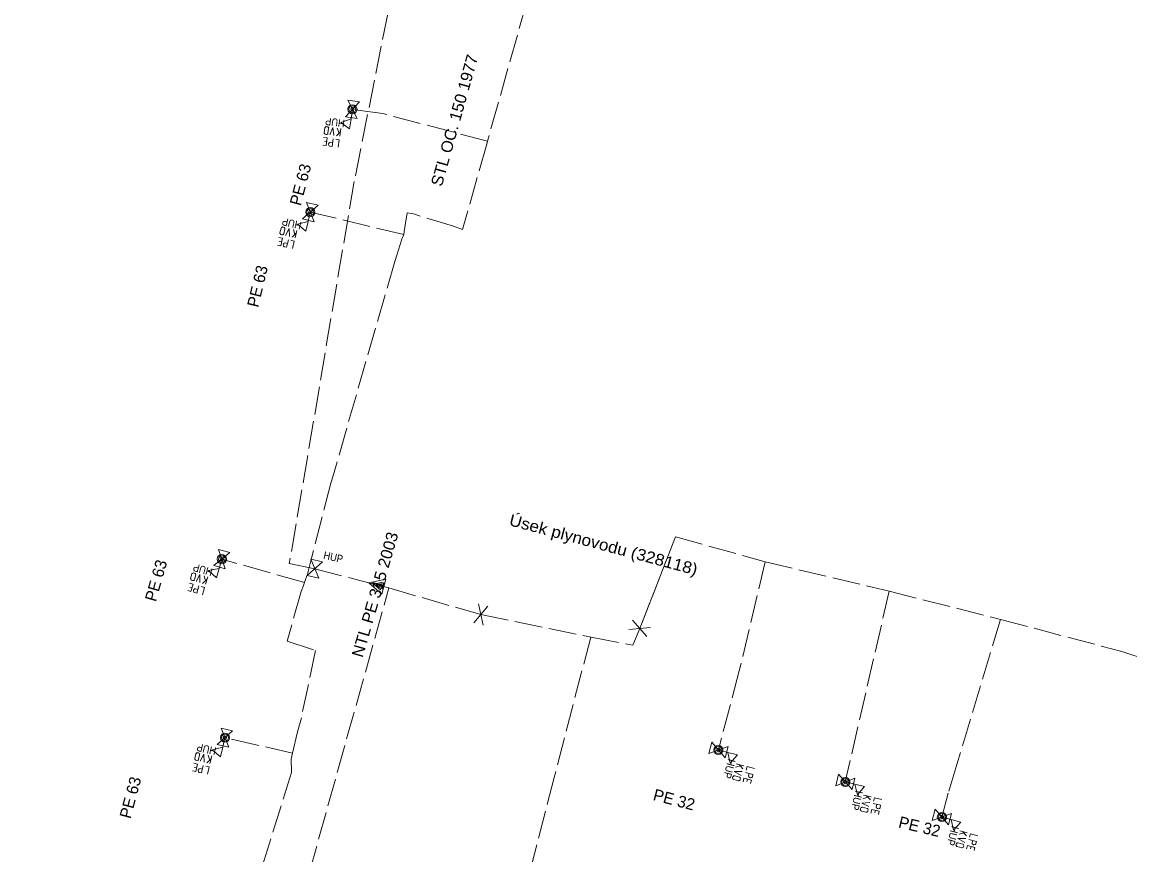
# Model space of a CAD drawing. Extents: x -688140 to -687678, y -1056859 to -1056384.
# Drawn here: x -688074.2 to -688002.5, y -1056647.4 to -1056593.5 of the extents above; entities that cross this region are included whole.
import ezdxf
from ezdxf.enums import TextEntityAlignment as Align

# ---------------------------------------------------------------- set-up
doc = ezdxf.new("R2010")
doc.units = 0
doc.header["$LTSCALE"] = 0.3
doc.linetypes.add('LONG_DASHED', pattern=[7.5, 6, -1.5])
for name, color, linetype, lineweight in [('12', 7, 'Continuous', 13), ('13', 7, 'Continuous', 13), ('25', 7, 'Continuous', 13), ('35', 7, 'LONG_DASHED', 13), ('40', 7, 'LONG_DASHED', 13), ('50', 7, 'LONG_DASHED', 13)]:
    doc.layers.add(name, color=color, linetype=linetype, lineweight=lineweight)
doc.layers.add('15', color=7, linetype='Continuous')

msp = doc.modelspace()

# ---------------------------------------------------------------- linework, layer by layer
at = {"layer": '12'}
for p, q in [((-688053.288, -1056599.585), (-688052.372, -1056598.615)), ((-688052.372, -1056598.615), (-688053.134, -1056598.506)), ((-688052.526, -1056599.694), (-688053.134, -1056598.506)), ((-688052.83, -1056599.1), (-688052.919, -1056599.724)), ((-688052.526, -1056599.694), (-688053.288, -1056599.585)), ((-688054.662, -1056600.617), (-688054.618, -1056600.31)), ((-688054.371, -1056600.346), (-688054.414, -1056600.653)), ((-688053.611, -1056600.544), (-688053.853, -1056600.823)), ((-688053.686, -1056600.645), (-688053.812, -1056600.324)), ((-688053.655, -1056600.851), (-688053.584, -1056600.356)), ((-688054.65, -1056601.175), (-688054.492, -1056601.197)), ((-688054.265, -1056601.239), (-688054.107, -1056601.262)), ((-688056.061, -1056606.2), (-688055.059, -1056605.32)), ((-688055.059, -1056605.32), (-688055.807, -1056605.14)), ((-688055.313, -1056606.38), (-688055.807, -1056605.14)), ((-688055.56, -1056605.76), (-688055.707, -1056606.373)), ((-688055.313, -1056606.38), (-688056.061, -1056606.2)), ((-688057.526, -1056607.099), (-688057.454, -1056606.797)), ((-688057.211, -1056606.855), (-688057.283, -1056607.157)), ((-688056.473, -1056607.125), (-688056.74, -1056607.38)), ((-688056.557, -1056607.218), (-688056.653, -1056606.886)), ((-688056.545, -1056607.426), (-688056.429, -1056606.94)), ((-688057.567, -1056607.655), (-688057.411, -1056607.692)), ((-688057.19, -1056607.755), (-688057.034, -1056607.792)), ((-688061.809, -1056628.649), (-688060.771, -1056627.811)), ((-688060.771, -1056627.811), (-688061.511, -1056627.601)), ((-688061.069, -1056628.859), (-688061.511, -1056627.601)), ((-688061.069, -1056628.859), (-688061.809, -1056628.649)), ((-688061.29, -1056628.23), (-688061.462, -1056628.836)), ((-688063.31, -1056629.486), (-688063.225, -1056629.188)), ((-688062.985, -1056629.256), (-688063.07, -1056629.554)), ((-688062.347, -1056629.645), (-688062.428, -1056629.31)), ((-688062.344, -1056629.854), (-688062.207, -1056629.373)), ((-688063.374, -1056630.039), (-688063.22, -1056630.083)), ((-688063.001, -1056630.156), (-688062.847, -1056630.199)), ((-688062.259, -1056629.556), (-688062.536, -1056629.799)), ((-688061.588, -1056640.235), (-688060.592, -1056639.345)), ((-688060.592, -1056639.345), (-688061.343, -1056639.172)), ((-688060.837, -1056640.408), (-688061.343, -1056639.172)), ((-688060.837, -1056640.408), (-688061.588, -1056640.235)), ((-688061.09, -1056639.79), (-688061.232, -1056640.404)), ((-688063.044, -1056641.146), (-688062.975, -1056640.843)), ((-688062.731, -1056640.9), (-688062.801, -1056641.202)), ((-688062.075, -1056641.256), (-688062.173, -1056640.926)), ((-688062.061, -1056641.465), (-688061.949, -1056640.977)), ((-688063.08, -1056641.702), (-688062.924, -1056641.738)), ((-688061.991, -1056641.163), (-688062.256, -1056641.42)), ((-688062.703, -1056641.799), (-688062.547, -1056641.835))]:
    msp.add_line(p, q, dxfattribs=at)
for points in [[(-688052.919, -1056599.724), (-688053.587, -1056599.952), (-688053.009, -1056600.357)], [(-688055.707, -1056606.373), (-688056.394, -1056606.537), (-688055.856, -1056606.995)], [(-688061.462, -1056628.836), (-688062.156, -1056628.972), (-688061.637, -1056629.452)], [(-688061.232, -1056640.404), (-688061.917, -1056640.574), (-688061.375, -1056641.028)]]:
    msp.add_lwpolyline(points, close=True, dxfattribs=at)
for points in [[(-688054.414, -1056600.653), (-688054.418, -1056600.682), (-688054.442, -1056600.709), (-688054.486, -1056600.733), (-688054.526, -1056600.728), (-688054.575, -1056600.721), (-688054.605, -1056600.716), (-688054.639, -1056600.671), (-688054.656, -1056600.648), (-688054.662, -1056600.617)], [(-688054.371, -1056600.346), (-688054.365, -1056600.306), (-688054.382, -1056600.283), (-688054.417, -1056600.248), (-688054.456, -1056600.233), (-688054.505, -1056600.225), (-688054.535, -1056600.221), (-688054.58, -1056600.255), (-688054.603, -1056600.272), (-688054.618, -1056600.31)], [(-688054.031, -1056600.798), (-688054.099, -1056600.283), (-688054.288, -1056600.761)], [(-688054.746, -1056601.423), (-688054.528, -1056601.454), (-688054.458, -1056600.959), (-688054.695, -1056600.926)], [(-688054.301, -1056601.487), (-688054.347, -1056601.46), (-688054.376, -1056601.375), (-688054.37, -1056601.336), (-688054.318, -1056601.252), (-688054.265, -1056601.239)], [(-688054.072, -1056601.014), (-688054.142, -1056601.509), (-688054.301, -1056601.487)], [(-688053.756, -1056601.564), (-688053.686, -1056601.069), (-688053.913, -1056601.037)], [(-688057.283, -1056607.157), (-688057.29, -1056607.186), (-688057.316, -1056607.211), (-688057.362, -1056607.23), (-688057.401, -1056607.221), (-688057.45, -1056607.21), (-688057.479, -1056607.203), (-688057.509, -1056607.154), (-688057.523, -1056607.13), (-688057.526, -1056607.099)], [(-688057.211, -1056606.855), (-688057.201, -1056606.817), (-688057.216, -1056606.792), (-688057.248, -1056606.754), (-688057.285, -1056606.735), (-688057.333, -1056606.723), (-688057.362, -1056606.716), (-688057.411, -1056606.746), (-688057.435, -1056606.761), (-688057.454, -1056606.797)], [(-688056.915, -1056607.338), (-688056.935, -1056606.819), (-688057.168, -1056607.277)], [(-688057.686, -1056607.893), (-688057.472, -1056607.945), (-688057.355, -1056607.458), (-688057.589, -1056607.402)], [(-688057.248, -1056607.998), (-688057.292, -1056607.967), (-688057.312, -1056607.88), (-688057.303, -1056607.841), (-688057.243, -1056607.763), (-688057.19, -1056607.755)], [(-688056.976, -1056607.549), (-688057.092, -1056608.036), (-688057.248, -1056607.998)], [(-688056.713, -1056608.126), (-688056.597, -1056607.64), (-688056.82, -1056607.587)], [(-688063.07, -1056629.554), (-688063.078, -1056629.583), (-688063.105, -1056629.606), (-688063.152, -1056629.624), (-688063.19, -1056629.613), (-688063.238, -1056629.6), (-688063.267, -1056629.591), (-688063.295, -1056629.542), (-688063.309, -1056629.517), (-688063.31, -1056629.486)], [(-688062.985, -1056629.256), (-688062.974, -1056629.217), (-688062.988, -1056629.193), (-688063.018, -1056629.153), (-688063.054, -1056629.132), (-688063.102, -1056629.119), (-688063.131, -1056629.111), (-688063.18, -1056629.138), (-688063.205, -1056629.152), (-688063.225, -1056629.188)], [(-688062.709, -1056629.75), (-688062.707, -1056629.231), (-688062.959, -1056629.679)], [(-688063.503, -1056630.273), (-688063.291, -1056630.333), (-688063.154, -1056629.852), (-688063.385, -1056629.787)], [(-688063.07, -1056630.396), (-688063.112, -1056630.363), (-688063.129, -1056630.275), (-688063.118, -1056630.237), (-688063.055, -1056630.161), (-688063.001, -1056630.156)], [(-688062.779, -1056629.959), (-688062.916, -1056630.44), (-688063.07, -1056630.396)], [(-688062.541, -1056630.546), (-688062.404, -1056630.065), (-688062.625, -1056630.003)], [(-688062.731, -1056640.9), (-688062.722, -1056640.861), (-688062.737, -1056640.837), (-688062.769, -1056640.798), (-688062.806, -1056640.78), (-688062.855, -1056640.769), (-688062.884, -1056640.762), (-688062.932, -1056640.792), (-688062.956, -1056640.807), (-688062.975, -1056640.843)], [(-688062.431, -1056641.379), (-688062.455, -1056640.861), (-688062.685, -1056641.321)], [(-688063.197, -1056641.942), (-688062.983, -1056641.991), (-688062.871, -1056641.504), (-688063.104, -1056641.45)], [(-688062.801, -1056641.202), (-688062.808, -1056641.231), (-688062.834, -1056641.256), (-688062.88, -1056641.276), (-688062.919, -1056641.267), (-688062.967, -1056641.256), (-688062.997, -1056641.249), (-688063.026, -1056641.201), (-688063.041, -1056641.177), (-688063.044, -1056641.146)], [(-688062.491, -1056641.591), (-688062.603, -1056642.079), (-688062.759, -1056642.043)], [(-688062.223, -1056642.166), (-688062.11, -1056641.679), (-688062.335, -1056641.627)], [(-688062.759, -1056642.043), (-688062.803, -1056642.012), (-688062.824, -1056641.925), (-688062.815, -1056641.886), (-688062.756, -1056641.807), (-688062.703, -1056641.799)]]:
    msp.add_lwpolyline(points, dxfattribs=at)
for centre, radius in [((-688052.83, -1056599.1), 0.297), ((-688052.83, -1056599.1), 0.223), ((-688052.83, -1056599.1), 0.223), ((-688052.83, -1056599.1), 0.112), ((-688055.56, -1056605.76), 0.297), ((-688055.56, -1056605.76), 0.223), ((-688055.56, -1056605.76), 0.223), ((-688055.56, -1056605.76), 0.112), ((-688061.29, -1056628.23), 0.297), ((-688061.29, -1056628.23), 0.223), ((-688061.29, -1056628.23), 0.223), ((-688061.29, -1056628.23), 0.112), ((-688061.09, -1056639.79), 0.297), ((-688061.09, -1056639.79), 0.223), ((-688061.09, -1056639.79), 0.223), ((-688061.09, -1056639.79), 0.112)]:
    msp.add_circle(centre, radius, dxfattribs=at)
at = {"layer": '13'}
for p, q in [((-688054.772, -1056628.405), (-688055.766, -1056629.295)), ((-688055.522, -1056628.233), (-688055.016, -1056629.467)), ((-688055.522, -1056628.233), (-688054.772, -1056628.405)), ((-688055.766, -1056629.295), (-688055.016, -1056629.467)), ((-688044.051, -1056631.279), (-688044.967, -1056632.361)), ((-688044.663, -1056631.128), (-688044.355, -1056632.512)), ((-688034.694, -1056632.192), (-688033.746, -1056633.246)), ((-688034.926, -1056632.777), (-688033.514, -1056632.661)), ((-688029.549, -1056640.079), (-688029.745, -1056640.823)), ((-688028.691, -1056641.101), (-688029.549, -1056640.079)), ((-688028.495, -1056640.357), (-688029.745, -1056640.823)), ((-688029.12, -1056640.59), (-688028.511, -1056640.751)), ((-688028.495, -1056640.357), (-688028.691, -1056641.101)), ((-688027.685, -1056641.62), (-688028.019, -1056641.708)), ((-688027.476, -1056641.613), (-688027.96, -1056641.485)), ((-688027.776, -1056641.534), (-688027.527, -1056641.806)), ((-688028.062, -1056642.265), (-688027.762, -1056642.344)), ((-688027.162, -1056642.264), (-688027.121, -1056642.11)), ((-688021.345, -1056642.163), (-688021.517, -1056642.913)), ((-688020.283, -1056642.407), (-688021.517, -1056642.913)), ((-688020.455, -1056643.157), (-688021.345, -1056642.163)), ((-688020.283, -1056642.407), (-688020.455, -1056643.157)), ((-688027.826, -1056642.586), (-688028.126, -1056642.507)), ((-688027.271, -1056642.639), (-688027.231, -1056642.484)), ((-688020.9, -1056642.66), (-688020.286, -1056642.801)), ((-688019.433, -1056643.644), (-688019.764, -1056643.742)), ((-688019.225, -1056643.63), (-688019.712, -1056643.518)), ((-688019.527, -1056643.561), (-688019.27, -1056643.825)), ((-688019.543, -1056644.614), (-688019.845, -1056644.544)), ((-688019.789, -1056644.301), (-688019.487, -1056644.37)), ((-688018.987, -1056644.649), (-688018.951, -1056644.493)), ((-688018.89, -1056644.271), (-688018.854, -1056644.115)), ((-688015.068, -1056644.418), (-688015.266, -1056645.162)), ((-688014.212, -1056645.442), (-688015.068, -1056644.418)), ((-688014.014, -1056644.698), (-688015.266, -1056645.162)), ((-688014.64, -1056644.93), (-688014.031, -1056645.092)), ((-688014.014, -1056644.698), (-688014.212, -1056645.442)), ((-688013.208, -1056645.963), (-688013.541, -1056646.05)), ((-688012.999, -1056645.957), (-688013.482, -1056645.828)), ((-688013.298, -1056645.877), (-688013.05, -1056646.15)), ((-688013.586, -1056646.608), (-688013.287, -1056646.687)), ((-688012.686, -1056646.609), (-688012.645, -1056646.455)), ((-688013.351, -1056646.929), (-688013.65, -1056646.849)), ((-688012.796, -1056646.983), (-688012.755, -1056646.829))]:
    msp.add_line(p, q, dxfattribs=at)
for points in [[(-688050.665, -1056629.527), (-688051.775, -1056629.761), (-688050.919, -1056630.505)], [(-688050.894, -1056629.731), (-688051.45, -1056629.845), (-688051.02, -1056630.215)], [(-688051.009, -1056629.836), (-688051.291, -1056629.886), (-688051.069, -1056630.068)], [(-688028.511, -1056640.751), (-688028.362, -1056641.441), (-688027.892, -1056640.914)], [(-688020.286, -1056642.801), (-688020.115, -1056643.487), (-688019.662, -1056642.945)], [(-688014.031, -1056645.092), (-688013.884, -1056645.783), (-688013.413, -1056645.257)]]:
    msp.add_lwpolyline(points, close=True, dxfattribs=at)
for points in [[(-688026.78, -1056641.796), (-688027.264, -1056641.669), (-688027.322, -1056641.891)], [(-688028.062, -1056642.265), (-688028.101, -1056642.255), (-688028.125, -1056642.269), (-688028.164, -1056642.3), (-688028.184, -1056642.336), (-688028.197, -1056642.385), (-688028.205, -1056642.414), (-688028.176, -1056642.463), (-688028.162, -1056642.487), (-688028.126, -1056642.507)], [(-688027.573, -1056641.98), (-688028.093, -1056641.988), (-688027.64, -1056642.232)], [(-688027.762, -1056642.344), (-688027.733, -1056642.352), (-688027.709, -1056642.379), (-688027.691, -1056642.425), (-688027.701, -1056642.464), (-688027.714, -1056642.512), (-688027.721, -1056642.541), (-688027.77, -1056642.57), (-688027.795, -1056642.584), (-688027.826, -1056642.586)], [(-688027.035, -1056642.763), (-688026.979, -1056642.551), (-688027.463, -1056642.423), (-688027.524, -1056642.655)], [(-688027.363, -1056642.046), (-688026.88, -1056642.174), (-688026.92, -1056642.328)], [(-688026.92, -1056642.328), (-688026.953, -1056642.371), (-688027.04, -1056642.39), (-688027.079, -1056642.38), (-688027.156, -1056642.318), (-688027.162, -1056642.264)], [(-688018.523, -1056643.791), (-688019.01, -1056643.679), (-688019.062, -1056643.904)], [(-688019.789, -1056644.301), (-688019.828, -1056644.292), (-688019.852, -1056644.307), (-688019.891, -1056644.339), (-688019.909, -1056644.376), (-688019.92, -1056644.424), (-688019.927, -1056644.454), (-688019.897, -1056644.502), (-688019.882, -1056644.526), (-688019.845, -1056644.544)], [(-688019.31, -1056644), (-688019.829, -1056644.025), (-688019.368, -1056644.254)], [(-688019.487, -1056644.37), (-688019.458, -1056644.377), (-688019.433, -1056644.403), (-688019.413, -1056644.449), (-688019.422, -1056644.488), (-688019.433, -1056644.536), (-688019.44, -1056644.566), (-688019.488, -1056644.596), (-688019.512, -1056644.611), (-688019.543, -1056644.614)], [(-688018.747, -1056644.766), (-688018.698, -1056644.552), (-688019.185, -1056644.44), (-688019.239, -1056644.673)], [(-688019.098, -1056644.059), (-688018.61, -1056644.171), (-688018.646, -1056644.327)], [(-688018.646, -1056644.327), (-688018.677, -1056644.372), (-688018.764, -1056644.393), (-688018.803, -1056644.384), (-688018.882, -1056644.325), (-688018.89, -1056644.271)], [(-688012.303, -1056646.142), (-688012.786, -1056646.013), (-688012.846, -1056646.236)], [(-688013.586, -1056646.608), (-688013.625, -1056646.597), (-688013.649, -1056646.611), (-688013.689, -1056646.642), (-688013.708, -1056646.679), (-688013.721, -1056646.727), (-688013.729, -1056646.756), (-688013.701, -1056646.805), (-688013.687, -1056646.829), (-688013.65, -1056646.849)], [(-688013.097, -1056646.324), (-688013.616, -1056646.331), (-688013.164, -1056646.575)], [(-688013.287, -1056646.687), (-688013.258, -1056646.695), (-688013.234, -1056646.722), (-688013.215, -1056646.769), (-688013.225, -1056646.807), (-688013.238, -1056646.855), (-688013.246, -1056646.884), (-688013.295, -1056646.913), (-688013.319, -1056646.927), (-688013.351, -1056646.929)], [(-688012.887, -1056646.39), (-688012.404, -1056646.519), (-688012.445, -1056646.674)], [(-688012.445, -1056646.674), (-688012.477, -1056646.717), (-688012.564, -1056646.735), (-688012.603, -1056646.724), (-688012.68, -1056646.663), (-688012.686, -1056646.609)], [(-688012.56, -1056647.108), (-688012.504, -1056646.896), (-688012.987, -1056646.767), (-688013.049, -1056646.999)]]:
    msp.add_lwpolyline(points, dxfattribs=at)
for centre, radius in [((-688029.12, -1056640.59), 0.297), ((-688029.12, -1056640.59), 0.223), ((-688029.12, -1056640.59), 0.223), ((-688029.12, -1056640.59), 0.112), ((-688020.9, -1056642.66), 0.297), ((-688020.9, -1056642.66), 0.223), ((-688020.9, -1056642.66), 0.223), ((-688020.9, -1056642.66), 0.112), ((-688014.64, -1056644.93), 0.297), ((-688014.64, -1056644.93), 0.223), ((-688014.64, -1056644.93), 0.223), ((-688014.64, -1056644.93), 0.112)]:
    msp.add_circle(centre, radius, dxfattribs=at)
at = {"layer": '25'}
msp.add_line((-688034.22, -1056632.719), (-688032.398, -1056628.063), dxfattribs=at)
at = {"layer": '35'}
msp.add_lwpolyline([(-688039.697, -1056585.644), (-688044.02, -1056600.96), (-688044.08, -1056601.16), (-688044.13, -1056601.35), (-688045.69, -1056606.89), (-688046.29, -1056606.68), (-688048.869, -1056605.881), (-688049, -1056605.84), (-688049.29, -1056605.81), (-688049.48, -1056607.02), (-688049.51, -1056607.21), (-688049.59, -1056607.4), (-688049.63, -1056607.5), (-688049.636, -1056607.517), (-688049.96, -1056608.54), (-688050.08, -1056608.95), (-688054.17, -1056623.12), (-688054.222, -1056623.32), (-688055.48, -1056628.16), (-688055.75, -1056629.21), (-688055.87, -1056629.55), (-688055.94, -1056629.75), (-688056.01, -1056629.93), (-688056.16, -1056630.32), (-688057.06, -1056633.55), (-688055.22, -1056634.14), (-688056.14, -1056638.5), (-688056.39, -1056639.41), (-688056.71, -1056640.8), (-688056.8, -1056641.18), (-688056.782, -1056641.973), (-688056.78, -1056642.05), (-688058.85, -1056648.66)], dxfattribs=at)
at = {"layer": '40'}
for points in [[(-688095.06, -1056535.93), (-688095.038, -1056535.924), (-688071.56, -1056533.616), (-688071.564, -1056549.067), (-688071.589, -1056554.63), (-688071.932, -1056562.234), (-688071.572, -1056572.516), (-688067.674, -1056575.945), (-688047.289, -1056577.08), (-688049.203, -1056586.191), (-688052.709, -1056603.772), (-688056.92, -1056628.52)], [(-688050.47, -1056630.1), (-688044.509, -1056631.82), (-688037.39, -1056633.28), (-688037.358, -1056633.286), (-688034.661, -1056633.811), (-688034.22, -1056632.719), (-688032.398, -1056628.063), (-688031.9, -1056626.79), (-688026.09, -1056628.4), (-688018.06, -1056630.31), (-688010.84, -1056632.13), (-688002.98, -1056634.21), (-687999.74, -1056635.29), (-687994.13, -1056636.66), (-687993.912, -1056636.718), (-687967.53, -1056643.76), (-687964.46, -1056646.48), (-687964.27, -1056647.42), (-687955.109, -1056650.11), (-687948.391, -1056652.074), (-687946.08, -1056652.75), (-687945.2, -1056652.67), (-687939.04, -1056649.24)], [(-688056.92, -1056628.52), (-688055.269, -1056628.85), (-688051.281, -1056629.889), (-688050.47, -1056630.1)], [(-688065.38, -1056676.24), (-688063.51, -1056676.71), (-688050.47, -1056630.1)]]:
    msp.add_lwpolyline(points, dxfattribs=at)
at = {"layer": '50'}
for p, q in [((-688049.51, -1056607.21), (-688055.56, -1056605.76)), ((-688018.06, -1056630.31), (-688020.9, -1056642.66)), ((-688056.71, -1056640.8), (-688061.09, -1056639.79))]:
    msp.add_line(p, q, dxfattribs=at)
for points in [[(-688044.08, -1056601.16), (-688050.86, -1056599.38), (-688052.83, -1056599.1)], [(-688055.94, -1056629.75), (-688056, -1056629.733), (-688061.29, -1056628.23)], [(-688026.09, -1056628.4), (-688027.77, -1056635.47), (-688029.12, -1056640.59)], [(-688010.84, -1056632.13), (-688013.67, -1056641.54), (-688014.23, -1056643.39), (-688014.64, -1056644.93)], [(-688037.39, -1056633.28), (-688039.76, -1056642.38), (-688043.27, -1056656.04), (-688042.07, -1056656.26)]]:
    msp.add_lwpolyline(points, dxfattribs=at)

# ---------------------------------------------------------------- texts
at = {"layer": '12', "width": 0.9}
for rotation, p in [(171.91, (-688053.926, -1056599.702)), (166.524, (-688056.707, -1056606.257)), (164.141, (-688062.456, -1056628.679)), (167.017, (-688062.233, -1056640.296))]:
    msp.add_text('HUP', height=0.5, rotation=rotation, dxfattribs=at).set_placement(p, align=Align.CENTER)
at = {"layer": '13', "width": 0.9}
for rotation, p in [(347.045, (-688054.127, -1056628.343)), (255.229, (-688028.65, -1056641.748)), (257.051, (-688020.393, -1056643.802)), (255.091, (-688014.172, -1056646.089))]:
    msp.add_text('HUP', height=0.5, rotation=rotation, dxfattribs=at).set_placement(p, align=Align.CENTER)
at = {"layer": '15'}
for s, rotation, width, p in [('STL OC. 150 1977', 74.378, 1.05, (-688047.039, -1056604.148)), ('Úsek plynovodu (328118)', 344.997, 1.1, (-688042.73, -1056626.03)), ('NTL PE 315 2003', 73.9, 1.05, (-688052.169, -1056634.65))]:
    msp.add_text(s, height=0.75, rotation=rotation, dxfattribs=dict(at, width=width)).set_placement(p)
for s, rotation, p in [('PE 63', 75.29, (-688056.181, -1056605.394)), ('PE 63', 76.522, (-688058.934, -1056611.975)), ('PE 63', 74.14, (-688065.566, -1056631.033)), ('PE 63', 75, (-688067.207, -1056645.084)), ('PE 32', 345.229, (-688033.404, -1056643.818)), ('PE 32', 346.61, (-688017.505, -1056645.598))]:
    msp.add_text(s, height=0.75, rotation=rotation, dxfattribs=at).set_placement(p)

doc.saveas('drawing.dxf')
